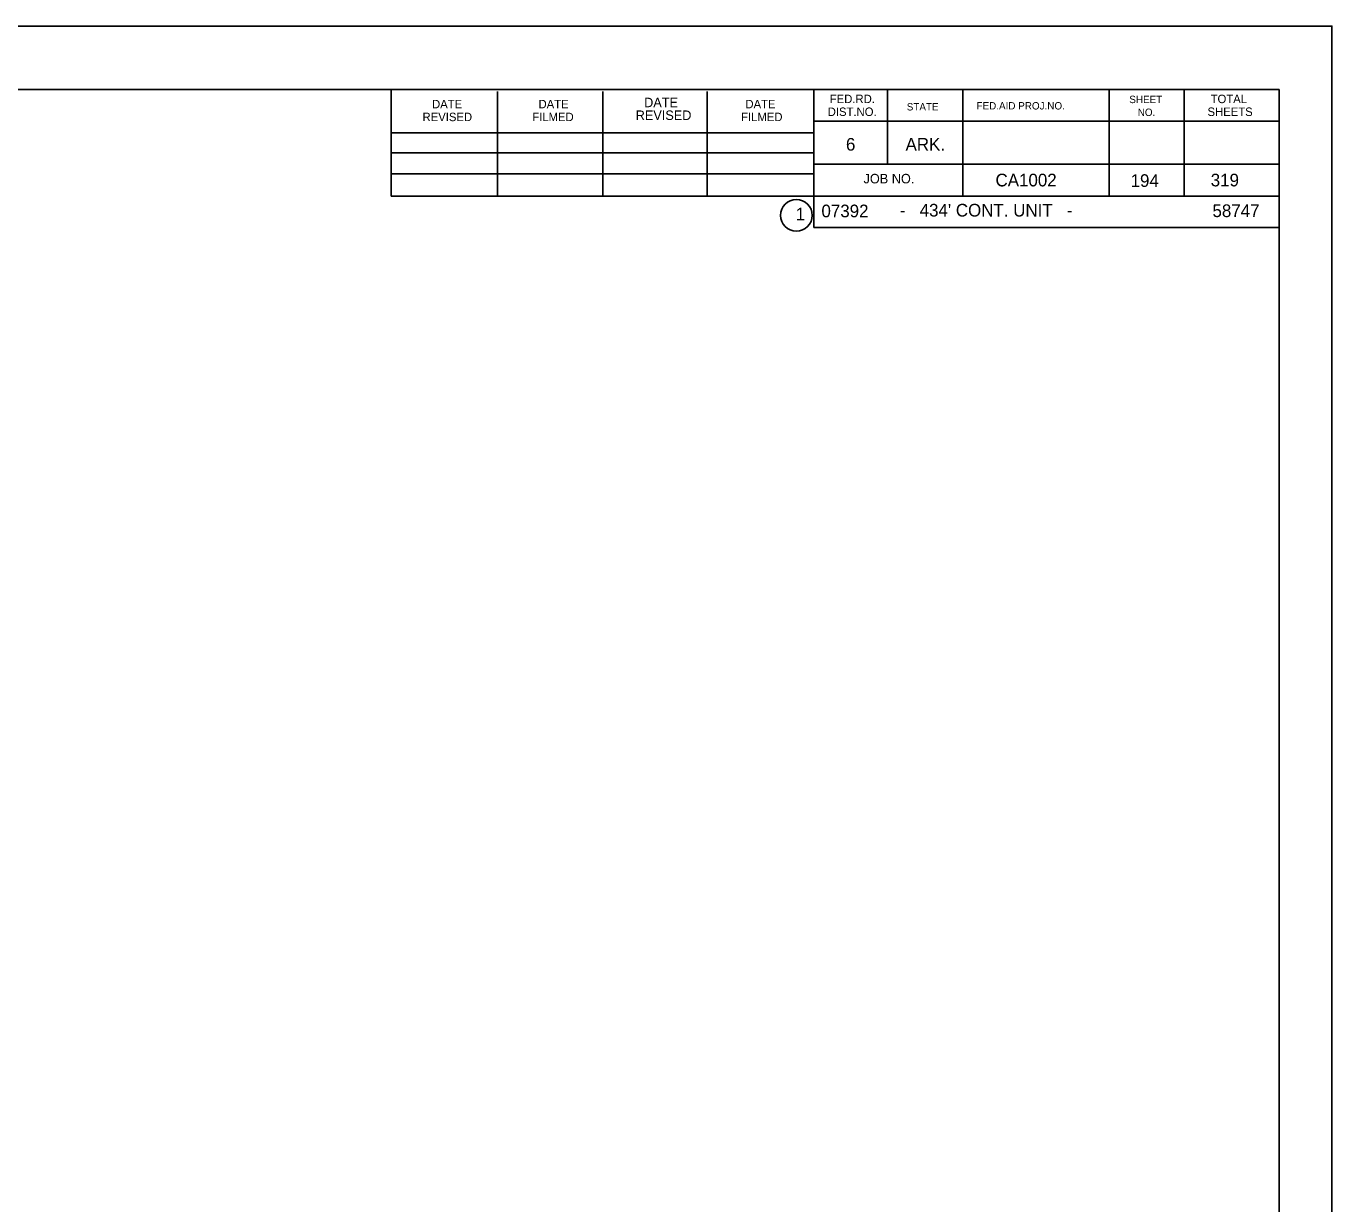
# Model space of a CAD drawing. Extents: x 208.7 to 242.8, y 328.9 to 350.7.
# Drawn here: x 230.69 to 242.78, y 339.81 to 350.71 of the extents above; entities that cross this region are included whole.
import ezdxf

# ---------------------------------------------------------------- set-up
doc = ezdxf.new("R2010")
doc.units = 0
for name, color, linetype in [('border', 7, 'Continuous'), ('Border 2660-Hwy18 - Level 62', 7, 'Continuous'), ('Border 2660-Hwy18 - Text', 7, 'Continuous'), ('Bridge No BLFR', 7, 'Continuous'), ('Text', 7, 'Continuous'), ('Title Text', 7, 'Continuous')]:
    doc.layers.add(name, color=color, linetype=linetype)

msp = doc.modelspace()

# ---------------------------------------------------------------- linework, layer by layer
at = {"layer": 'border'}
for p, q in [((210.28, 350.129), (242.291, 350.129)), ((234.065, 349.142), (234.065, 350.129)), ((235.05, 349.142), (235.05, 350.11)), ((236.027, 349.142), (236.027, 350.11)), ((236.994, 349.142), (236.994, 350.11)), ((237.98, 350.129), (237.98, 348.85)), ((238.664, 350.129), (238.664, 349.436)), ((239.359, 350.129), (239.359, 349.142)), ((240.716, 350.129), (240.716, 349.142)), ((241.411, 350.129), (241.411, 349.142)), ((242.291, 329.584), (242.291, 350.129)), ((242.291, 349.835), (237.98, 349.835)), ((242.291, 349.838), (242.291, 349.838)), ((234.065, 349.727), (237.98, 349.727)), ((234.065, 349.541), (237.98, 349.541)), ((234.065, 349.142), (234.065, 349.348)), ((234.065, 349.348), (237.98, 349.348)), ((242.291, 349.436), (237.98, 349.436)), ((238.277, 349.436), (242.291, 349.436)), ((242.291, 349.142), (234.065, 349.142)), ((237.98, 348.85), (242.291, 348.85))]:
    msp.add_line(p, q, dxfattribs=at)
msp.add_circle((237.819, 348.963), 0.147, dxfattribs=at)
at = {"layer": 'Border 2660-Hwy18 - Level 62'}
msp.add_lwpolyline([(208.659, 350.715), (242.778, 350.715), (242.778, 328.905), (208.659, 328.905)], close=True, dxfattribs=at)

# ---------------------------------------------------------------- texts
at = {"layer": 'Border 2660-Hwy18 - Text'}
for s, height, p in [('FED.RD.', 0.0782, (238.128, 350.002)), ('SHEET', 0.0684, (240.902, 350.002)), ('TOTAL', 0.0782, (241.655, 350.002)), ('DATE', 0.0782, (234.445, 349.954)), ('DATE', 0.0782, (235.431, 349.954)), ('DATE', 0.0879, (236.409, 349.964)), ('DATE', 0.0782, (237.347, 349.954)), ('DIST.NO.', 0.0782, (238.109, 349.883)), ('STATE', 0.0684, (238.841, 349.934)), ('FED.AID PROJ.NO.', 0.06839, (239.487, 349.943)), ('NO.', 0.0684, (240.98, 349.883)), ('SHEETS', 0.0782, (241.626, 349.883)), ('REVISED', 0.0782, (234.357, 349.835)), ('FILMED', 0.0782, (235.373, 349.835)), ('REVISED', 0.0879, (236.331, 349.846)), ('FILMED', 0.0782, (237.307, 349.835)), ('6', 0.117, (238.278, 349.562)), ('ARK.', 0.1172, (238.83, 349.562)), ('JOB NO.', 0.0879, (238.441, 349.259)), ('CA1002', 0.1172, (239.663, 349.231)), ('319', 0.1172, (241.656, 349.231)), ('1', 0.117, (237.812, 348.916))]:
    msp.add_text(s, height=height, dxfattribs=at).set_placement(p)
at = {"layer": 'Bridge No BLFR'}
msp.add_text('07392', height=0.1172, dxfattribs=at).set_placement((238.051, 348.945))
at = {"layer": 'Text'}
msp.add_text('194', height=0.1172, dxfattribs=at).set_placement((240.914, 349.226))
at = {"layer": 'Title Text'}
for s, height, p in [("   -   434' CONT. UNIT   -", 0.11722, (238.647, 348.952)), ('58747', 0.1172, (241.672, 348.947))]:
    msp.add_text(s, height=height, dxfattribs=at).set_placement(p)

doc.saveas('drawing.dxf')
